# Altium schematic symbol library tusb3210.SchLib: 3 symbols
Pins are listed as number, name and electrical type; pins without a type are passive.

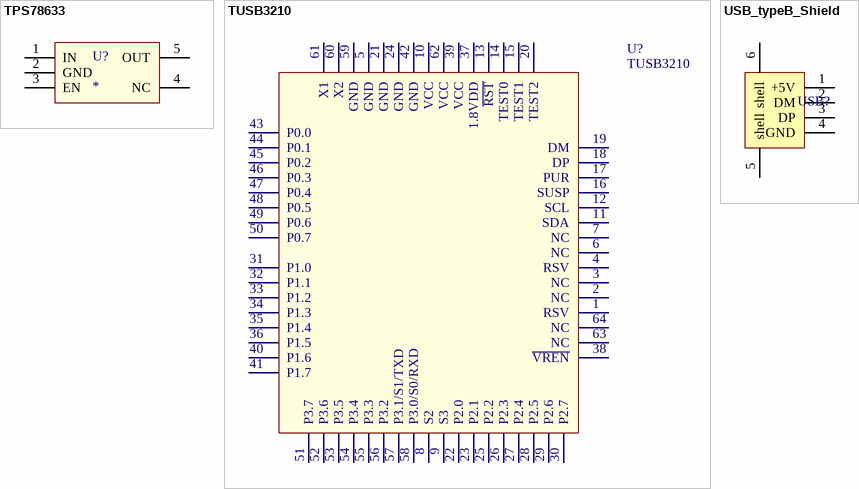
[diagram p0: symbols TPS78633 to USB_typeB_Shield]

## TPS78633
designator U?
3.3V Power
pins: 1 IN, 2 GND, 3 EN, 4 NC, 5 OUT

## TUSB3210
designator U?
footprint Quad64
pins: 1 RSV, 2 NC, 3 NC, 4 RSV, 5 GND, 6 NC, 7 NC, 8 S2, 9 S3, 10 VCC, 11 SDA, 12 SCL, 13 ~{RST}, 14 TEST0, 15 TEST1, 16 SUSP, 17 PUR, 18 DP, 19 DM, 20 TEST2, 21 GND, 22 P2.0, 23 P2.1, 24 GND, 25 P2.2, 26 P2.3, 27 P2.4, 28 P2.5, 29 P2.6, 30 P2.7, 31 P1.0, 32 P1.1, 33 P1.2, 34 P1.3, 35 P1.4, 36 P1.5, 37 1.8VDD, 38 ~{VREN}, 39 VCC, 40 P1.6, 41 P1.7, 42 GND, 43 P0.0, 44 P0.1, 45 P0.2, 46 P0.3, 47 P0.4, 48 P0.5, 49 P0.6, 50 P0.7, 51 P3.7, 52 P3.6, 53 P3.5, 54 P3.4, 55 P3.3, 56 P3.2, 57 P3.1/S1/TXD, 58 P3.0/S0/RXD, 59 GND, 60 X2, 61 X1, 62 VCC, 63 NC, 64 NC

## USB_typeB_Shield
designator USB?  (value not drawn)
footprint USB-A
pins: 1 +5V, 2 DM, 3 DP, 4 GND, 5 shell, 6 shell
